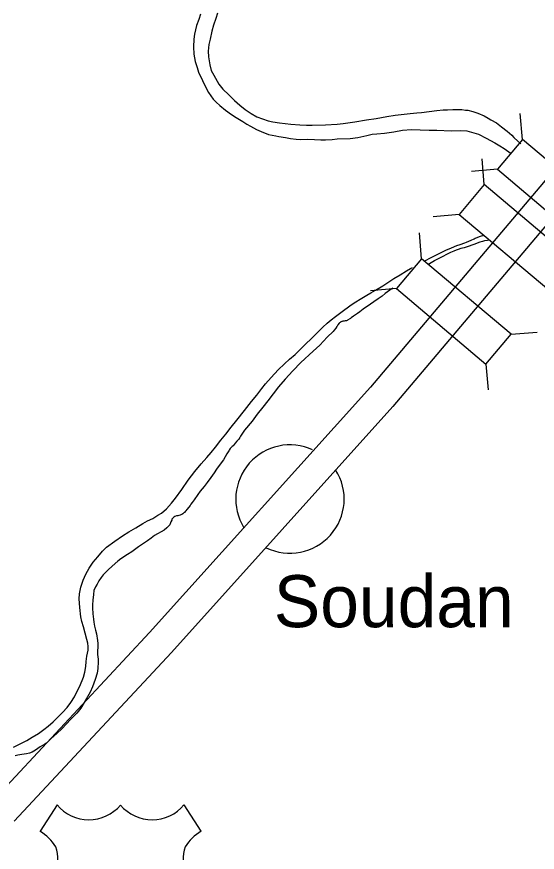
# Model space of a CAD drawing. Extents: x -939622 to -934222, y 1383701 to 1385301.
# Drawn here: x -935735.82 to -935719.98, y 1384208.15 to 1384233.59 of the extents above; entities that cross this region are included whole.
import ezdxf

# ---------------------------------------------------------------- set-up
doc = ezdxf.new("R2010")
doc.units = 0
for name, color, linetype in [('Level 15', 7, 'Continuous'), ('Level 20', 7, 'Continuous'), ('Level 22', 7, 'Continuous'), ('Level 24', 7, 'Continuous'), ('Level 9', 7, 'Continuous')]:
    doc.layers.add(name, color=color, linetype=linetype)

msp = doc.modelspace()

# ---------------------------------------------------------------- linework, layer by layer
at = {"layer": 'Level 15'}
for points in [[(-935714.56, 1384232.198), (-935716.48, 1384231.356), (-935716.709, 1384231.279), (-935716.88, 1384231.2), (-935717.061, 1384231.105), (-935717.296, 1384230.953), (-935717.638, 1384230.723), (-935717.862, 1384230.564), (-935718.162, 1384230.273), (-935718.378, 1384230.094), (-935718.589, 1384229.934), (-935718.928, 1384229.609), (-935719.266, 1384229.221), (-935719.517, 1384228.868), (-935725.058, 1384222.319), (-935731.78, 1384214.846), (-935736.547, 1384209.73)], [(-935714.198, 1384231.374), (-935716.154, 1384230.516), (-935716.375, 1384230.442), (-935716.482, 1384230.392), (-935716.607, 1384230.327), (-935716.801, 1384230.201), (-935717.127, 1384229.982), (-935717.285, 1384229.871), (-935717.56, 1384229.603), (-935717.818, 1384229.388), (-935718.004, 1384229.247), (-935718.276, 1384228.987), (-935718.558, 1384228.664), (-935718.806, 1384228.315), (-935724.38, 1384221.727), (-935731.117, 1384214.238), (-935735.906, 1384209.098)]]:
    msp.add_lwpolyline(points, dxfattribs=at)
at = {"layer": 'Level 20'}
for p, q in [((-935720.428, 1384229.856), (-935720.495, 1384230.645)), ((-935721.592, 1384228.48), (-935721.659, 1384229.269)), ((-935721.193, 1384228.947), (-935721.982, 1384228.88)), ((-935722.357, 1384227.572), (-935723.146, 1384227.504)), ((-935723.501, 1384226.224), (-935723.568, 1384227.013)), ((-935724.266, 1384225.315), (-935725.055, 1384225.248)), ((-935720.775, 1384223.927), (-935719.986, 1384223.994)), ((-935721.541, 1384223.019), (-935721.473, 1384222.229))]:
    msp.add_line(p, q, dxfattribs=at)
for points in [[(-935721.193, 1384228.947), (-935718.468, 1384226.651), (-935717.702, 1384227.559), (-935720.428, 1384229.856)], [(-935718.866, 1384226.184), (-935721.592, 1384228.48), (-935722.357, 1384227.572), (-935719.632, 1384225.275)], [(-935720.775, 1384223.927), (-935723.501, 1384226.224), (-935724.266, 1384225.315), (-935721.541, 1384223.019)]]:
    msp.add_lwpolyline(points, close=True, dxfattribs=at)
at = {"layer": 'Level 22'}
for p, q in [((-935734.595, 1384209.596), (-935735.114, 1384208.793)), ((-935730.734, 1384209.596), (-935730.215, 1384208.793))]:
    msp.add_line(p, q, dxfattribs=at)
for centre, radius, start, end in [((-935733.628, 1384210.41), 1.264, 220.075, 319.6701), ((-935731.701, 1384210.41), 1.264, 220.3299, 319.925), ((-935735.792, 1384207.627), 1.349, 30.7809, 59.9883), ((-935729.536, 1384207.627), 1.349, 120.0117, 149.2191), ((-935735.496, 1384207.983), 0.925, 328.8105, 21.2108), ((-935729.833, 1384207.983), 0.925, 158.7892, 211.1895)]:
    msp.add_arc(centre, radius, start, end, dxfattribs=at)
at = {"layer": 'Level 24'}
for start, end in [(65.2892, 211.9081), (243.8384, 32.6508)]:
    msp.add_arc((-935727.506, 1384218.908), 1.65, start, end, dxfattribs=at)
at = {"layer": 'Level 9'}
for points in [[(-935730.235, 1384233.668), (-935730.281, 1384233.513), (-935730.347, 1384233.325), (-935730.417, 1384233.061), (-935730.433, 1384232.907), (-935730.444, 1384232.675), (-935730.434, 1384232.458), (-935730.392, 1384232.234), (-935730.335, 1384232.046), (-935730.286, 1384231.906), (-935730.17, 1384231.651), (-935730.084, 1384231.476), (-935729.986, 1384231.289)], [(-935729.715, 1384233.702), (-935729.761, 1384233.544), (-935729.838, 1384233.337), (-935729.881, 1384233.158), (-935729.936, 1384232.913), (-935729.976, 1384232.746), (-935729.997, 1384232.544), (-935729.983, 1384232.37), (-935729.945, 1384232.124), (-935729.904, 1384231.957), (-935729.828, 1384231.812), (-935729.67, 1384231.54), (-935729.555, 1384231.387), (-935729.37, 1384231.212), (-935729.191, 1384231.04), (-935729.037, 1384230.903), (-935728.868, 1384230.773), (-935728.685, 1384230.643), (-935728.514, 1384230.543), (-935728.341, 1384230.485), (-935728.175, 1384230.427), (-935728.03, 1384230.392), (-935727.829, 1384230.359), (-935727.651, 1384230.338), (-935727.477, 1384230.322), (-935727.207, 1384230.303), (-935727.006, 1384230.292)], [(-935729.986, 1384231.289), (-935729.913, 1384231.18), (-935729.845, 1384231.086), (-935729.758, 1384230.989), (-935729.641, 1384230.888), (-935729.472, 1384230.751), (-935729.283, 1384230.616), (-935729.145, 1384230.524), (-935728.944, 1384230.4), (-935728.822, 1384230.323), (-935728.706, 1384230.257), (-935728.526, 1384230.163), (-935728.387, 1384230.096), (-935728.156, 1384230.012), (-935727.939, 1384229.965), (-935727.846, 1384229.947), (-935727.639, 1384229.92), (-935727.491, 1384229.888), (-935727.314, 1384229.864), (-935727.188, 1384229.853), (-935726.987, 1384229.862), (-935726.762, 1384229.854), (-935726.565, 1384229.845), (-935726.43, 1384229.84), (-935726.224, 1384229.852), (-935726.071, 1384229.872), (-935725.674, 1384229.884), (-935725.441, 1384229.918), (-935725.17, 1384229.975), (-935725.007, 1384230.013), (-935724.864, 1384230.032), (-935724.631, 1384230.052), (-935724.35, 1384230.084), (-935724.08, 1384230.135), (-935723.808, 1384230.164), (-935723.547, 1384230.145), (-935723.265, 1384230.139), (-935723.032, 1384230.14), (-935722.597, 1384230.123), (-935722.313, 1384230.132), (-935722.127, 1384230.117), (-935721.91, 1384230.057), (-935721.765, 1384230.016), (-935721.53, 1384229.894), (-935721.266, 1384229.752), (-935721.122, 1384229.666), (-935720.985, 1384229.58), (-935720.776, 1384229.425)], [(-935727.006, 1384230.292), (-935726.833, 1384230.291), (-935726.426, 1384230.306), (-935726.07, 1384230.32), (-935725.885, 1384230.338), (-935725.536, 1384230.391), (-935725.176, 1384230.45), (-935724.887, 1384230.492), (-935724.554, 1384230.56), (-935724.303, 1384230.6), (-935724.026, 1384230.63), (-935723.847, 1384230.645), (-935723.644, 1384230.663), (-935723.5, 1384230.682), (-935723.271, 1384230.707), (-935723.035, 1384230.739), (-935722.841, 1384230.757), (-935722.709, 1384230.761), (-935722.548, 1384230.772), (-935722.428, 1384230.772), (-935722.275, 1384230.765), (-935722.167, 1384230.753), (-935722.089, 1384230.744), (-935721.945, 1384230.712), (-935721.784, 1384230.657), (-935721.599, 1384230.578), (-935721.477, 1384230.504), (-935721.389, 1384230.449), (-935721.215, 1384230.361), (-935721.068, 1384230.245), (-935720.899, 1384230.109), (-935720.758, 1384229.984), (-935720.69, 1384229.911), (-935720.57, 1384229.8), (-935720.483, 1384229.721)], [(-935723.423, 1384226.146), (-935723.422, 1384226.146), (-935723.187, 1384226.274), (-935722.942, 1384226.399), (-935722.759, 1384226.486), (-935722.593, 1384226.554), (-935722.431, 1384226.625), (-935722.33, 1384226.662), (-935722.188, 1384226.708), (-935722.129, 1384226.731), (-935721.987, 1384226.795), (-935721.904, 1384226.834), (-935721.872, 1384226.847), (-935721.807, 1384226.873), (-935721.733, 1384226.906), (-935721.709, 1384226.912), (-935721.679, 1384226.919), (-935721.641, 1384226.933), (-935721.63, 1384226.935)], [(-935721.446, 1384226.793), (-935721.492, 1384226.781), (-935721.582, 1384226.766), (-935721.647, 1384226.749), (-935721.73, 1384226.725), (-935721.807, 1384226.696), (-935721.881, 1384226.669), (-935721.97, 1384226.634), (-935722.047, 1384226.604), (-935722.145, 1384226.577), (-935722.207, 1384226.56), (-935722.302, 1384226.533), (-935722.388, 1384226.506), (-935722.45, 1384226.483), (-935722.521, 1384226.454), (-935722.616, 1384226.412), (-935722.746, 1384226.351), (-935722.858, 1384226.293), (-935722.973, 1384226.232), (-935723.094, 1384226.175), (-935723.105, 1384226.162), (-935723.308, 1384226.042)], [(-935723.838, 1384225.926), (-935723.772, 1384225.96)], [(-935735.923, 1384211.356), (-935735.723, 1384211.458), (-935735.519, 1384211.555), (-935735.349, 1384211.659), (-935735.166, 1384211.773), (-935735.002, 1384211.887), (-935734.868, 1384211.996), (-935734.719, 1384212.127), (-935734.559, 1384212.273), (-935734.428, 1384212.41), (-935734.289, 1384212.565), (-935734.174, 1384212.71), (-935734.063, 1384212.888), (-935733.97, 1384213.077), (-935733.908, 1384213.214), (-935733.791, 1384213.489), (-935733.75, 1384213.64), (-935733.723, 1384213.81), (-935733.706, 1384213.964), (-935733.687, 1384214.124), (-935733.654, 1384214.312), (-935733.651, 1384214.417), (-935733.663, 1384214.516), (-935733.691, 1384214.635), (-935733.741, 1384214.823), (-935733.795, 1384215.014), (-935733.842, 1384215.184), (-935733.87, 1384215.322), (-935733.9, 1384215.604), (-935733.923, 1384215.868), (-935733.91, 1384216.022), (-935733.871, 1384216.225), (-935733.797, 1384216.441), (-935733.718, 1384216.618), (-935733.619, 1384216.801), (-935733.496, 1384216.983), (-935733.357, 1384217.153), (-935733.21, 1384217.32), (-935733.088, 1384217.438), (-935732.836, 1384217.623), (-935732.601, 1384217.784), (-935732.413, 1384217.913), (-935732.196, 1384218.034), (-935731.981, 1384218.161), (-935731.84, 1384218.243), (-935731.683, 1384218.318), (-935731.528, 1384218.413), (-935731.419, 1384218.482), (-935731.261, 1384218.61), (-935731.117, 1384218.78), (-935730.989, 1384218.932), (-935730.803, 1384219.202), (-935730.605, 1384219.479), (-935730.398, 1384219.75), (-935730.21, 1384219.985), (-935730.042, 1384220.171), (-935729.903, 1384220.325), (-935729.773, 1384220.483), (-935729.612, 1384220.702), (-935729.459, 1384220.887), (-935729.298, 1384221.096), (-935729.128, 1384221.309), (-935728.891, 1384221.608), (-935728.681, 1384221.874), (-935728.519, 1384222.068), (-935728.367, 1384222.272), (-935728.249, 1384222.42), (-935728.084, 1384222.608), (-935727.869, 1384222.847), (-935727.671, 1384223.027), (-935727.517, 1384223.168), (-935727.351, 1384223.311), (-935727.228, 1384223.429), (-935727.06, 1384223.591), (-935726.821, 1384223.827), (-935726.72, 1384223.932), (-935726.598, 1384224.047), (-935726.502, 1384224.141), (-935726.371, 1384224.265), (-935726.254, 1384224.362), (-935726.123, 1384224.471), (-935725.914, 1384224.619), (-935725.689, 1384224.786), (-935725.551, 1384224.88), (-935725.322, 1384225.026), (-935725.166, 1384225.115), (-935725.042, 1384225.185), (-935724.907, 1384225.264), (-935724.681, 1384225.4), (-935724.343, 1384225.619), (-935724.149, 1384225.739), (-935723.958, 1384225.853), (-935723.838, 1384225.926)], [(-935724.379, 1384225.331), (-935724.467, 1384225.269), (-935724.608, 1384225.165), (-935724.704, 1384225.09), (-935724.822, 1384225.008), (-935724.95, 1384224.914), (-935725.056, 1384224.841), (-935725.276, 1384224.687), (-935725.381, 1384224.612), (-935725.452, 1384224.561), (-935725.51, 1384224.52), (-935725.572, 1384224.476), (-935725.639, 1384224.429), (-935725.668, 1384224.407), (-935725.686, 1384224.398), (-935725.754, 1384224.353), (-935725.765, 1384224.347), (-935725.783, 1384224.337), (-935725.81, 1384224.334), (-935725.825, 1384224.333), (-935725.855, 1384224.329), (-935725.896, 1384224.319), (-935725.914, 1384224.315), (-935725.929, 1384224.309), (-935725.944, 1384224.302), (-935725.959, 1384224.299), (-935725.982, 1384224.286), (-935726, 1384224.274), (-935726.014, 1384224.261), (-935726.049, 1384224.212), (-935726.071, 1384224.172), (-935726.08, 1384224.157)], [(-935726.08, 1384224.157), (-935726.114, 1384224.107), (-935726.158, 1384224.055), (-935726.189, 1384224.009), (-935726.37, 1384223.835), (-935726.602, 1384223.593), (-935726.8, 1384223.406), (-935727.172, 1384223.061), (-935727.422, 1384222.809), (-935727.648, 1384222.559), (-935727.853, 1384222.324), (-935728.02, 1384222.108), (-935728.185, 1384221.901), (-935728.335, 1384221.71), (-935728.502, 1384221.488), (-935728.66, 1384221.276), (-935728.891, 1384221.001)], [(-935728.891, 1384221.001), (-935729.008, 1384220.819), (-935729.031, 1384220.786), (-935729.068, 1384220.736), (-935729.12, 1384220.672), (-935729.172, 1384220.607), (-935729.21, 1384220.566), (-935729.239, 1384220.532), (-935729.262, 1384220.508), (-935729.294, 1384220.477), (-935729.326, 1384220.445), (-935729.361, 1384220.399), (-935729.372, 1384220.381), (-935729.389, 1384220.35), (-935729.412, 1384220.319), (-935729.432, 1384220.286), (-935729.528, 1384220.102)], [(-935729.528, 1384220.102), (-935729.635, 1384219.973), (-935729.741, 1384219.813), (-935729.815, 1384219.702), (-935729.919, 1384219.567), (-935730.028, 1384219.413), (-935730.117, 1384219.293), (-935730.236, 1384219.145), (-935730.313, 1384219.049), (-935730.425, 1384218.886), (-935730.483, 1384218.803), (-935730.52, 1384218.754), (-935730.549, 1384218.708), (-935730.638, 1384218.596), (-935730.647, 1384218.59), (-935730.678, 1384218.547), (-935730.699, 1384218.525), (-935730.722, 1384218.501), (-935730.739, 1384218.488), (-935730.771, 1384218.457), (-935730.801, 1384218.438), (-935730.827, 1384218.425), (-935730.848, 1384218.421), (-935730.887, 1384218.411), (-935730.925, 1384218.401), (-935730.958, 1384218.394), (-935731.012, 1384218.377), (-935731.041, 1384218.361), (-935731.076, 1384218.33), (-935731.099, 1384218.296), (-935731.107, 1384218.263), (-935731.129, 1384218.217), (-935731.151, 1384218.156), (-935731.168, 1384218.12), (-935731.2, 1384218.08), (-935731.25, 1384218.033), (-935731.337, 1384217.964), (-935731.631, 1384217.795), (-935731.728, 1384217.717), (-935731.845, 1384217.632), (-935731.962, 1384217.551), (-935732.118, 1384217.449), (-935732.317, 1384217.305), (-935732.452, 1384217.219), (-935732.658, 1384217.084), (-935732.742, 1384217.018), (-935732.921, 1384216.868), (-935733.043, 1384216.753), (-935733.145, 1384216.653), (-935733.191, 1384216.598), (-935733.257, 1384216.515), (-935733.32, 1384216.419), (-935733.371, 1384216.315), (-935733.428, 1384216.235), (-935733.476, 1384216.123), (-935733.487, 1384216.002), (-935733.506, 1384215.83), (-935733.513, 1384215.685), (-935733.519, 1384215.595), (-935733.511, 1384215.414), (-935733.491, 1384215.252), (-935733.476, 1384215.163), (-935733.455, 1384215.04), (-935733.427, 1384214.911), (-935733.4, 1384214.804), (-935733.367, 1384214.606), (-935733.355, 1384214.513), (-935733.353, 1384214.453), (-935733.355, 1384214.417), (-935733.362, 1384214.269), (-935733.362, 1384214.161), (-935733.354, 1384214.11), (-935733.343, 1384214.026), (-935733.344, 1384213.954), (-935733.353, 1384213.752), (-935733.375, 1384213.61), (-935733.432, 1384213.412), (-935733.518, 1384213.193), (-935733.591, 1384213.028), (-935733.739, 1384212.768), (-935733.875, 1384212.538), (-935733.991, 1384212.384), (-935734.183, 1384212.201), (-935734.31, 1384212.067), (-935734.446, 1384211.916), (-935734.606, 1384211.766), (-935734.784, 1384211.604), (-935734.921, 1384211.477), (-935734.965, 1384211.442), (-935735.112, 1384211.363), (-935735.25, 1384211.262), (-935735.353, 1384211.205), (-935735.436, 1384211.172), (-935735.528, 1384211.154), (-935735.599, 1384211.143), (-935735.668, 1384211.135), (-935735.787, 1384211.11), (-935735.873, 1384211.089)]]:
    msp.add_lwpolyline(points, dxfattribs=at)

# ---------------------------------------------------------------- texts
at = {"layer": 'Level 24'}
msp.add_text('Soudan', height=1.584, dxfattribs=at).set_placement((-935727.999, 1384215.006))

doc.saveas('drawing.dxf')
